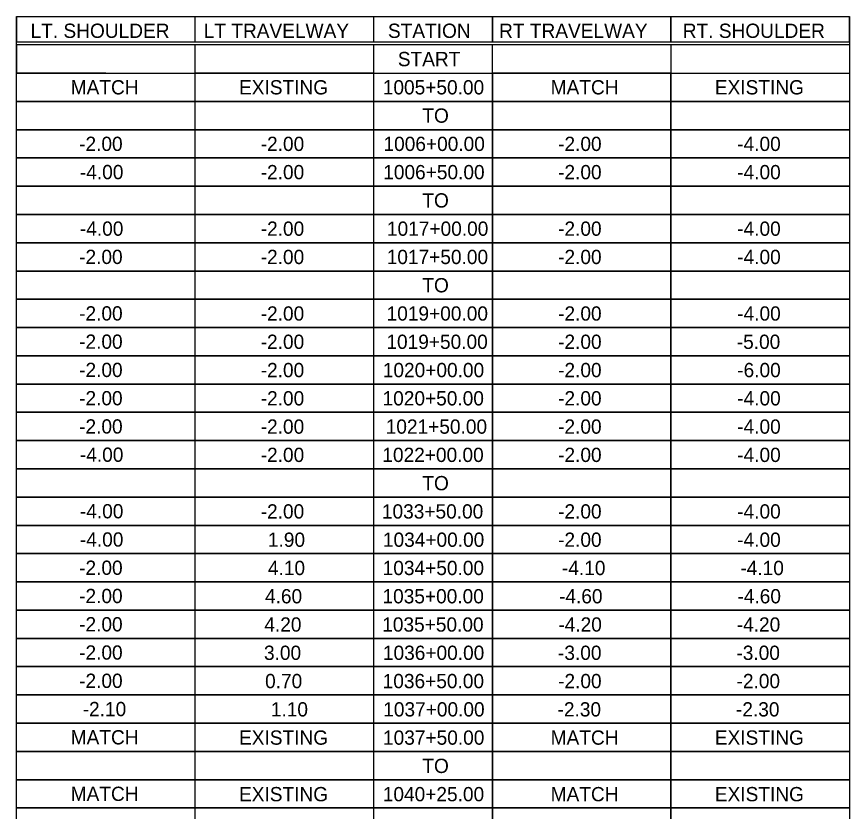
# Model space of a CAD drawing. Extents: x 1026502 to 1027102, y 781811 to 782040.
# Drawn here: x 1027034.42 to 1027062.42, y 781893.52 to 781920.24 of the extents above; entities that cross this region are included whole.
import ezdxf

# ---------------------------------------------------------------- set-up
doc = ezdxf.new("R2010")
doc.units = 0
for name, color, linetype in [('ANNOTATION', 7, 'Continuous'), ('BORDER', 7, 'Continuous'), ('DIMENSIONS', 7, 'Continuous')]:
    doc.layers.add(name, color=color, linetype=linetype)

msp = doc.modelspace()

# ---------------------------------------------------------------- linework, layer by layer
at = {"layer": 'ANNOTATION'}
msp.add_lwpolyline([(1027034.415, 781920.244), (1027062.415, 781920.244), (1027062.415, 781866.071), (1027034.415, 781866.071)], close=True, dxfattribs=at)
at = {"layer": 'BORDER'}
for p, q in [((1027034.415, 781920.244), (1027034.415, 781919.399)), ((1027037.415, 781919.293), (1027034.415, 781919.293)), ((1027034.415, 781919.293), (1027034.415, 781918.343)), ((1027062.415, 781919.293), (1027062.415, 781918.343)), ((1027037.415, 781918.343), (1027034.415, 781918.343)), ((1027037.415, 781918.343), (1027034.415, 781918.343)), ((1027037.415, 781917.393), (1027034.415, 781917.393)), ((1027037.415, 781917.393), (1027034.415, 781917.393)), ((1027037.415, 781917.393), (1027040.415, 781917.393)), ((1027037.415, 781916.442), (1027034.415, 781916.442)), ((1027037.415, 781916.442), (1027034.415, 781916.442)), ((1027037.415, 781916.442), (1027040.415, 781916.442)), ((1027037.415, 781915.492), (1027034.415, 781915.492)), ((1027037.415, 781915.492), (1027034.415, 781915.492)), ((1027037.415, 781915.492), (1027040.415, 781915.492)), ((1027037.415, 781914.541), (1027034.415, 781914.541)), ((1027037.415, 781914.541), (1027034.415, 781914.541)), ((1027037.415, 781914.541), (1027040.415, 781914.541)), ((1027037.415, 781913.591), (1027034.415, 781913.591)), ((1027037.415, 781913.591), (1027034.415, 781913.591)), ((1027037.415, 781913.591), (1027040.415, 781913.591)), ((1027037.415, 781912.641), (1027034.415, 781912.641)), ((1027037.415, 781912.641), (1027034.415, 781912.641)), ((1027037.415, 781912.641), (1027040.415, 781912.641)), ((1027037.415, 781911.69), (1027034.415, 781911.69)), ((1027037.415, 781911.69), (1027034.415, 781911.69)), ((1027037.415, 781911.69), (1027040.415, 781911.69)), ((1027037.415, 781910.74), (1027034.415, 781910.74)), ((1027037.415, 781910.74), (1027034.415, 781910.74)), ((1027037.415, 781910.74), (1027040.415, 781910.74)), ((1027037.415, 781909.789), (1027034.415, 781909.789)), ((1027037.415, 781909.789), (1027034.415, 781909.789)), ((1027037.415, 781909.789), (1027040.415, 781909.789)), ((1027037.415, 781908.839), (1027034.415, 781908.839)), ((1027037.415, 781908.839), (1027034.415, 781908.839)), ((1027037.415, 781908.839), (1027040.415, 781908.839)), ((1027037.415, 781907.889), (1027034.415, 781907.889)), ((1027037.415, 781907.889), (1027034.415, 781907.889)), ((1027037.415, 781907.889), (1027040.415, 781907.889)), ((1027037.415, 781906.938), (1027034.415, 781906.938)), ((1027037.415, 781906.938), (1027034.415, 781906.938)), ((1027037.415, 781906.938), (1027040.415, 781906.938)), ((1027037.415, 781905.988), (1027034.415, 781905.988)), ((1027037.415, 781905.988), (1027034.415, 781905.988)), ((1027037.415, 781905.988), (1027040.415, 781905.988)), ((1027037.415, 781905.037), (1027034.415, 781905.037)), ((1027037.415, 781905.037), (1027034.415, 781905.037)), ((1027037.415, 781905.037), (1027040.415, 781905.037)), ((1027037.415, 781904.087), (1027034.415, 781904.087)), ((1027037.415, 781904.087), (1027034.415, 781904.087)), ((1027037.415, 781904.087), (1027040.415, 781904.087)), ((1027037.415, 781903.137), (1027034.415, 781903.137)), ((1027037.415, 781903.137), (1027034.415, 781903.137)), ((1027037.415, 781903.137), (1027040.415, 781903.137)), ((1027037.415, 781902.186), (1027034.415, 781902.186)), ((1027037.415, 781902.186), (1027034.415, 781902.186)), ((1027037.415, 781902.186), (1027040.415, 781902.186)), ((1027037.415, 781901.236), (1027034.415, 781901.236)), ((1027037.415, 781901.236), (1027034.415, 781901.236)), ((1027037.415, 781901.236), (1027040.415, 781901.236)), ((1027037.415, 781900.285), (1027034.415, 781900.285)), ((1027037.415, 781900.285), (1027034.415, 781900.285)), ((1027037.415, 781900.285), (1027040.415, 781900.285)), ((1027037.415, 781899.335), (1027034.415, 781899.335)), ((1027037.415, 781899.335), (1027034.415, 781899.335)), ((1027037.415, 781899.335), (1027040.415, 781899.335)), ((1027037.415, 781898.385), (1027034.415, 781898.385)), ((1027037.415, 781898.385), (1027034.415, 781898.385)), ((1027037.415, 781898.385), (1027040.415, 781898.385)), ((1027037.415, 781897.434), (1027034.415, 781897.434)), ((1027037.415, 781897.434), (1027034.415, 781897.434)), ((1027037.415, 781897.434), (1027040.415, 781897.434)), ((1027037.415, 781896.484), (1027034.415, 781896.484)), ((1027037.415, 781896.484), (1027034.415, 781896.484)), ((1027037.415, 781896.484), (1027040.415, 781896.484)), ((1027037.415, 781895.533), (1027034.415, 781895.533)), ((1027037.415, 781895.533), (1027034.415, 781895.533)), ((1027037.415, 781895.533), (1027040.415, 781895.533)), ((1027037.415, 781894.583), (1027034.415, 781894.583)), ((1027037.415, 781894.583), (1027034.415, 781894.583)), ((1027037.415, 781894.583), (1027040.415, 781894.583)), ((1027037.415, 781893.633), (1027034.415, 781893.633)), ((1027037.415, 781893.633), (1027034.415, 781893.633)), ((1027037.415, 781893.633), (1027040.415, 781893.633))]:
    msp.add_line(p, q, dxfattribs=at)
for points in [[(1027034.415, 781920.244), (1027062.415, 781920.244), (1027062.415, 781919.293), (1027034.415, 781919.293)], [(1027034.415, 781918.343), (1027062.415, 781918.343), (1027062.415, 781917.393), (1027034.415, 781917.393)], [(1027034.415, 781917.393), (1027062.415, 781917.393), (1027062.415, 781916.442), (1027034.415, 781916.442)], [(1027034.415, 781916.442), (1027062.415, 781916.442), (1027062.415, 781915.492), (1027034.415, 781915.492)], [(1027034.415, 781915.492), (1027062.415, 781915.492), (1027062.415, 781914.541), (1027034.415, 781914.541)], [(1027034.415, 781914.541), (1027062.415, 781914.541), (1027062.415, 781913.591), (1027034.415, 781913.591)], [(1027034.415, 781913.591), (1027062.415, 781913.591), (1027062.415, 781912.641), (1027034.415, 781912.641)], [(1027034.415, 781912.641), (1027062.415, 781912.641), (1027062.415, 781911.69), (1027034.415, 781911.69)], [(1027034.415, 781911.69), (1027062.415, 781911.69), (1027062.415, 781910.74), (1027034.415, 781910.74)], [(1027034.415, 781910.74), (1027062.415, 781910.74), (1027062.415, 781909.789), (1027034.415, 781909.789)], [(1027034.415, 781909.789), (1027062.415, 781909.789), (1027062.415, 781908.839), (1027034.415, 781908.839)], [(1027034.415, 781908.839), (1027062.415, 781908.839), (1027062.415, 781907.889), (1027034.415, 781907.889)], [(1027034.415, 781907.889), (1027062.415, 781907.889), (1027062.415, 781906.938), (1027034.415, 781906.938)], [(1027034.415, 781906.938), (1027062.415, 781906.938), (1027062.415, 781905.988), (1027034.415, 781905.988)], [(1027034.415, 781905.988), (1027062.415, 781905.988), (1027062.415, 781905.037), (1027034.415, 781905.037)], [(1027034.415, 781905.037), (1027062.415, 781905.037), (1027062.415, 781904.087), (1027034.415, 781904.087)], [(1027034.415, 781904.087), (1027062.415, 781904.087), (1027062.415, 781903.137), (1027034.415, 781903.137)], [(1027034.415, 781903.137), (1027062.415, 781903.137), (1027062.415, 781902.186), (1027034.415, 781902.186)], [(1027034.415, 781902.186), (1027062.415, 781902.186), (1027062.415, 781901.236), (1027034.415, 781901.236)], [(1027034.415, 781901.236), (1027062.415, 781901.236), (1027062.415, 781900.285), (1027034.415, 781900.285)], [(1027034.415, 781900.285), (1027062.415, 781900.285), (1027062.415, 781899.335), (1027034.415, 781899.335)], [(1027034.415, 781899.335), (1027062.415, 781899.335), (1027062.415, 781898.385), (1027034.415, 781898.385)], [(1027034.415, 781898.385), (1027062.415, 781898.385), (1027062.415, 781897.434), (1027034.415, 781897.434)], [(1027034.415, 781897.434), (1027062.415, 781897.434), (1027062.415, 781896.484), (1027034.415, 781896.484)], [(1027034.415, 781896.484), (1027062.415, 781896.484), (1027062.415, 781895.533), (1027034.415, 781895.533)], [(1027034.415, 781895.533), (1027062.415, 781895.533), (1027062.415, 781894.583), (1027034.415, 781894.583)], [(1027034.415, 781894.583), (1027062.415, 781894.583), (1027062.415, 781893.633), (1027034.415, 781893.633)], [(1027034.415, 781893.633), (1027062.415, 781893.633), (1027062.415, 781892.682), (1027034.415, 781892.682)]]:
    msp.add_lwpolyline(points, close=True, dxfattribs=at)
for points in [[(1027034.415, 781919.399), (1027062.415, 781919.399), (1027062.415, 781920.244)], [(1027040.415, 781919.399), (1027040.415, 781920.244)], [(1027046.415, 781920.244), (1027046.415, 781919.399)], [(1027050.415, 781920.244), (1027050.415, 781919.399)], [(1027050.415, 781919.399), (1027050.415, 781920.244)], [(1027056.415, 781920.244), (1027056.415, 781919.399)], [(1027056.415, 781919.399), (1027056.415, 781920.244)], [(1027062.415, 781920.244), (1027062.415, 781919.399)], [(1027046.415, 781919.293), (1027046.415, 781918.343), (1027040.415, 781918.343), (1027040.415, 781919.293)], [(1027056.415, 781919.293), (1027056.415, 781918.343), (1027050.415, 781918.343), (1027050.415, 781919.293)], [(1027046.415, 781918.343), (1027046.415, 781917.393), (1027040.415, 781917.393), (1027040.415, 781918.343)], [(1027050.415, 781918.343), (1027050.415, 781917.393), (1027046.415, 781917.393)], [(1027056.415, 781918.343), (1027056.415, 781917.393), (1027050.415, 781917.393), (1027050.415, 781918.343)], [(1027062.415, 781918.343), (1027062.415, 781917.393), (1027056.415, 781917.393), (1027056.415, 781918.343)], [(1027046.415, 781917.393), (1027046.415, 781916.442), (1027040.415, 781916.442), (1027040.415, 781917.393)], [(1027050.415, 781917.393), (1027050.415, 781916.442), (1027046.415, 781916.442)], [(1027056.415, 781917.393), (1027056.415, 781916.442), (1027050.415, 781916.442), (1027050.415, 781917.393)], [(1027062.415, 781917.393), (1027062.415, 781916.442), (1027056.415, 781916.442), (1027056.415, 781917.393)], [(1027046.415, 781916.442), (1027046.415, 781915.492), (1027040.415, 781915.492), (1027040.415, 781916.442)], [(1027050.415, 781916.442), (1027050.415, 781915.492), (1027046.415, 781915.492)], [(1027056.415, 781916.442), (1027056.415, 781915.492), (1027050.415, 781915.492), (1027050.415, 781916.442)], [(1027062.415, 781916.442), (1027062.415, 781915.492), (1027056.415, 781915.492), (1027056.415, 781916.442)], [(1027046.415, 781915.492), (1027046.415, 781914.541), (1027040.415, 781914.541), (1027040.415, 781915.492)], [(1027050.415, 781915.492), (1027050.415, 781914.541), (1027046.415, 781914.541)], [(1027056.415, 781915.492), (1027056.415, 781914.541), (1027050.415, 781914.541), (1027050.415, 781915.492)], [(1027062.415, 781915.492), (1027062.415, 781914.541), (1027056.415, 781914.541), (1027056.415, 781915.492)], [(1027046.415, 781914.541), (1027046.415, 781913.591), (1027040.415, 781913.591), (1027040.415, 781914.541)], [(1027050.415, 781914.541), (1027050.415, 781913.591), (1027046.415, 781913.591)], [(1027056.415, 781914.541), (1027056.415, 781913.591), (1027050.415, 781913.591), (1027050.415, 781914.541)], [(1027062.415, 781914.541), (1027062.415, 781913.591), (1027056.415, 781913.591), (1027056.415, 781914.541)], [(1027046.415, 781913.591), (1027046.415, 781912.641), (1027040.415, 781912.641), (1027040.415, 781913.591)], [(1027050.415, 781913.591), (1027050.415, 781912.641), (1027046.415, 781912.641)], [(1027056.415, 781913.591), (1027056.415, 781912.641), (1027050.415, 781912.641), (1027050.415, 781913.591)], [(1027062.415, 781913.591), (1027062.415, 781912.641), (1027056.415, 781912.641), (1027056.415, 781913.591)], [(1027046.415, 781912.641), (1027046.415, 781911.69), (1027040.415, 781911.69), (1027040.415, 781912.641)], [(1027050.415, 781912.641), (1027050.415, 781911.69), (1027046.415, 781911.69)], [(1027056.415, 781912.641), (1027056.415, 781911.69), (1027050.415, 781911.69), (1027050.415, 781912.641)], [(1027062.415, 781912.641), (1027062.415, 781911.69), (1027056.415, 781911.69), (1027056.415, 781912.641)], [(1027046.415, 781911.69), (1027046.415, 781910.74), (1027040.415, 781910.74), (1027040.415, 781911.69)], [(1027050.415, 781911.69), (1027050.415, 781910.74), (1027046.415, 781910.74)], [(1027056.415, 781911.69), (1027056.415, 781910.74), (1027050.415, 781910.74), (1027050.415, 781911.69)], [(1027062.415, 781911.69), (1027062.415, 781910.74), (1027056.415, 781910.74), (1027056.415, 781911.69)], [(1027046.415, 781910.74), (1027046.415, 781909.789), (1027040.415, 781909.789), (1027040.415, 781910.74)], [(1027050.415, 781910.74), (1027050.415, 781909.789), (1027046.415, 781909.789)], [(1027056.415, 781910.74), (1027056.415, 781909.789), (1027050.415, 781909.789), (1027050.415, 781910.74)], [(1027062.415, 781910.74), (1027062.415, 781909.789), (1027056.415, 781909.789), (1027056.415, 781910.74)], [(1027046.415, 781909.789), (1027046.415, 781908.839), (1027040.415, 781908.839), (1027040.415, 781909.789)], [(1027050.415, 781909.789), (1027050.415, 781908.839), (1027046.415, 781908.839)], [(1027056.415, 781909.789), (1027056.415, 781908.839), (1027050.415, 781908.839), (1027050.415, 781909.789)], [(1027062.415, 781909.789), (1027062.415, 781908.839), (1027056.415, 781908.839), (1027056.415, 781909.789)], [(1027046.415, 781908.839), (1027046.415, 781907.889), (1027040.415, 781907.889), (1027040.415, 781908.839)], [(1027050.415, 781908.839), (1027050.415, 781907.889), (1027046.415, 781907.889)], [(1027056.415, 781908.839), (1027056.415, 781907.889), (1027050.415, 781907.889), (1027050.415, 781908.839)], [(1027062.415, 781908.839), (1027062.415, 781907.889), (1027056.415, 781907.889), (1027056.415, 781908.839)], [(1027046.415, 781907.889), (1027046.415, 781906.938), (1027040.415, 781906.938), (1027040.415, 781907.889)], [(1027050.415, 781907.889), (1027050.415, 781906.938), (1027046.415, 781906.938)], [(1027056.415, 781907.889), (1027056.415, 781906.938), (1027050.415, 781906.938), (1027050.415, 781907.889)], [(1027062.415, 781907.889), (1027062.415, 781906.938), (1027056.415, 781906.938), (1027056.415, 781907.889)], [(1027046.415, 781906.938), (1027046.415, 781905.988), (1027040.415, 781905.988), (1027040.415, 781906.938)], [(1027050.415, 781906.938), (1027050.415, 781905.988), (1027046.415, 781905.988)], [(1027056.415, 781906.938), (1027056.415, 781905.988), (1027050.415, 781905.988), (1027050.415, 781906.938)], [(1027062.415, 781906.938), (1027062.415, 781905.988), (1027056.415, 781905.988), (1027056.415, 781906.938)], [(1027046.415, 781905.988), (1027046.415, 781905.037), (1027040.415, 781905.037), (1027040.415, 781905.988)], [(1027050.415, 781905.988), (1027050.415, 781905.037), (1027046.415, 781905.037)], [(1027056.415, 781905.988), (1027056.415, 781905.037), (1027050.415, 781905.037), (1027050.415, 781905.988)], [(1027062.415, 781905.988), (1027062.415, 781905.037), (1027056.415, 781905.037), (1027056.415, 781905.988)], [(1027046.415, 781905.037), (1027046.415, 781904.087), (1027040.415, 781904.087), (1027040.415, 781905.037)], [(1027050.415, 781905.037), (1027050.415, 781904.087), (1027046.415, 781904.087)], [(1027056.415, 781905.037), (1027056.415, 781904.087), (1027050.415, 781904.087), (1027050.415, 781905.037)], [(1027062.415, 781905.037), (1027062.415, 781904.087), (1027056.415, 781904.087), (1027056.415, 781905.037)], [(1027046.415, 781904.087), (1027046.415, 781903.137), (1027040.415, 781903.137), (1027040.415, 781904.087)], [(1027050.415, 781904.087), (1027050.415, 781903.137), (1027046.415, 781903.137)], [(1027056.415, 781904.087), (1027056.415, 781903.137), (1027050.415, 781903.137), (1027050.415, 781904.087)], [(1027062.415, 781904.087), (1027062.415, 781903.137), (1027056.415, 781903.137), (1027056.415, 781904.087)], [(1027046.415, 781903.137), (1027046.415, 781902.186), (1027040.415, 781902.186), (1027040.415, 781903.137)], [(1027050.415, 781903.137), (1027050.415, 781902.186), (1027046.415, 781902.186)], [(1027056.415, 781903.137), (1027056.415, 781902.186), (1027050.415, 781902.186), (1027050.415, 781903.137)], [(1027062.415, 781903.137), (1027062.415, 781902.186), (1027056.415, 781902.186), (1027056.415, 781903.137)], [(1027046.415, 781902.186), (1027046.415, 781901.236), (1027040.415, 781901.236), (1027040.415, 781902.186)], [(1027050.415, 781902.186), (1027050.415, 781901.236), (1027046.415, 781901.236)], [(1027056.415, 781902.186), (1027056.415, 781901.236), (1027050.415, 781901.236), (1027050.415, 781902.186)], [(1027062.415, 781902.186), (1027062.415, 781901.236), (1027056.415, 781901.236), (1027056.415, 781902.186)], [(1027046.415, 781901.236), (1027046.415, 781900.285), (1027040.415, 781900.285), (1027040.415, 781901.236)], [(1027050.415, 781901.236), (1027050.415, 781900.285), (1027046.415, 781900.285)], [(1027056.415, 781901.236), (1027056.415, 781900.285), (1027050.415, 781900.285), (1027050.415, 781901.236)], [(1027062.415, 781901.236), (1027062.415, 781900.285), (1027056.415, 781900.285), (1027056.415, 781901.236)], [(1027046.415, 781900.285), (1027046.415, 781899.335), (1027040.415, 781899.335), (1027040.415, 781900.285)], [(1027050.415, 781900.285), (1027050.415, 781899.335), (1027046.415, 781899.335)], [(1027056.415, 781900.285), (1027056.415, 781899.335), (1027050.415, 781899.335), (1027050.415, 781900.285)], [(1027062.415, 781900.285), (1027062.415, 781899.335), (1027056.415, 781899.335), (1027056.415, 781900.285)], [(1027046.415, 781899.335), (1027046.415, 781898.385), (1027040.415, 781898.385), (1027040.415, 781899.335)], [(1027050.415, 781899.335), (1027050.415, 781898.385), (1027046.415, 781898.385)], [(1027056.415, 781899.335), (1027056.415, 781898.385), (1027050.415, 781898.385), (1027050.415, 781899.335)], [(1027062.415, 781899.335), (1027062.415, 781898.385), (1027056.415, 781898.385), (1027056.415, 781899.335)], [(1027046.415, 781898.385), (1027046.415, 781897.434), (1027040.415, 781897.434), (1027040.415, 781898.385)], [(1027050.415, 781898.385), (1027050.415, 781897.434), (1027046.415, 781897.434)], [(1027056.415, 781898.385), (1027056.415, 781897.434), (1027050.415, 781897.434), (1027050.415, 781898.385)], [(1027062.415, 781898.385), (1027062.415, 781897.434), (1027056.415, 781897.434), (1027056.415, 781898.385)], [(1027046.415, 781897.434), (1027046.415, 781896.484), (1027040.415, 781896.484), (1027040.415, 781897.434)], [(1027050.415, 781897.434), (1027050.415, 781896.484), (1027046.415, 781896.484)], [(1027056.415, 781897.434), (1027056.415, 781896.484), (1027050.415, 781896.484), (1027050.415, 781897.434)], [(1027062.415, 781897.434), (1027062.415, 781896.484), (1027056.415, 781896.484), (1027056.415, 781897.434)], [(1027046.415, 781896.484), (1027046.415, 781895.533), (1027040.415, 781895.533), (1027040.415, 781896.484)], [(1027050.415, 781896.484), (1027050.415, 781895.533), (1027046.415, 781895.533)], [(1027056.415, 781896.484), (1027056.415, 781895.533), (1027050.415, 781895.533), (1027050.415, 781896.484)], [(1027062.415, 781896.484), (1027062.415, 781895.533), (1027056.415, 781895.533), (1027056.415, 781896.484)], [(1027046.415, 781895.533), (1027046.415, 781894.583), (1027040.415, 781894.583), (1027040.415, 781895.533)], [(1027050.415, 781895.533), (1027050.415, 781894.583), (1027046.415, 781894.583)], [(1027056.415, 781895.533), (1027056.415, 781894.583), (1027050.415, 781894.583), (1027050.415, 781895.533)], [(1027062.415, 781895.533), (1027062.415, 781894.583), (1027056.415, 781894.583), (1027056.415, 781895.533)], [(1027046.415, 781894.583), (1027046.415, 781893.633), (1027040.415, 781893.633), (1027040.415, 781894.583)], [(1027050.415, 781894.583), (1027050.415, 781893.633), (1027046.415, 781893.633)], [(1027056.415, 781894.583), (1027056.415, 781893.633), (1027050.415, 781893.633), (1027050.415, 781894.583)], [(1027062.415, 781894.583), (1027062.415, 781893.633), (1027056.415, 781893.633), (1027056.415, 781894.583)], [(1027046.415, 781893.633), (1027046.415, 781892.682), (1027040.415, 781892.682), (1027040.415, 781893.633)], [(1027050.415, 781893.633), (1027050.415, 781892.682), (1027046.415, 781892.682)], [(1027056.415, 781893.633), (1027056.415, 781892.682), (1027050.415, 781892.682), (1027050.415, 781893.633)], [(1027062.415, 781893.633), (1027062.415, 781892.682), (1027056.415, 781892.682), (1027056.415, 781893.633)]]:
    msp.add_lwpolyline(points, dxfattribs=at)

# ---------------------------------------------------------------- texts
at = {"layer": 'DIMENSIONS'}
for s, p in [('LT. SHOULDER', (1027034.883, 781919.529)), ('LT TRAVELWAY', (1027040.706, 781919.529)), ('STATION', (1027046.9, 781919.529)), ('RT TRAVELWAY', (1027050.638, 781919.529)), ('RT. SHOULDER', (1027056.814, 781919.529)), ('START', (1027047.232, 781918.578)), ('MATCH', (1027036.233, 781917.628)), ('EXISTING', (1027041.892, 781917.628)), ('1005+50.00', (1027046.727, 781917.628)), ('MATCH', (1027052.372, 781917.628)), ('EXISTING', (1027057.892, 781917.628)), ('TO', (1027048.057, 781916.677)), ('-2.00', (1027036.516, 781915.727)), ('-2.00', (1027042.622, 781915.726)), ('1006+00.00', (1027046.75, 781915.726)), ('-2.00', (1027052.622, 781915.726)), ('-4.00', (1027058.645, 781915.726)), ('-4.00', (1027036.542, 781914.777)), ('-2.00', (1027042.622, 781914.775)), ('1006+50.00', (1027046.742, 781914.775)), ('-2.00', (1027052.622, 781914.775)), ('-4.00', (1027058.645, 781914.775)), ('TO', (1027048.057, 781913.824)), ('-4.00', (1027036.542, 781912.876)), ('-2.00', (1027042.622, 781912.874)), ('1017+00.00', (1027046.867, 781912.874)), ('-2.00', (1027052.622, 781912.874)), ('-4.00', (1027058.645, 781912.874)), ('-2.00', (1027036.516, 781911.925)), ('-2.00', (1027042.622, 781911.923)), ('1017+50.00', (1027046.859, 781911.923)), ('-2.00', (1027052.622, 781911.923)), ('-4.00', (1027058.645, 781911.923)), ('TO', (1027048.057, 781910.972)), ('-2.00', (1027036.516, 781910.025)), ('-2.00', (1027042.622, 781910.021)), ('1019+00.00', (1027046.855, 781910.021)), ('-2.00', (1027052.622, 781910.021)), ('-4.00', (1027058.645, 781910.021)), ('-2.00', (1027036.516, 781909.074)), ('-2.00', (1027042.622, 781909.07)), ('1019+50.00', (1027046.848, 781909.07)), ('-2.00', (1027052.622, 781909.07)), ('-5.00', (1027058.63, 781909.07)), ('-2.00', (1027036.516, 781908.124)), ('-2.00', (1027042.622, 781908.119)), ('1020+00.00', (1027046.727, 781908.119)), ('-2.00', (1027052.622, 781908.119)), ('-6.00', (1027058.645, 781908.119)), ('-2.00', (1027036.516, 781907.173)), ('-2.00', (1027042.622, 781907.169)), ('1020+50.00', (1027046.719, 781907.169)), ('-2.00', (1027052.622, 781907.169)), ('-4.00', (1027058.645, 781907.169)), ('-2.00', (1027036.516, 781906.223)), ('-2.00', (1027042.622, 781906.218)), ('1021+50.00', (1027046.825, 781906.218)), ('-2.00', (1027052.622, 781906.218)), ('-4.00', (1027058.645, 781906.218)), ('-4.00', (1027036.542, 781905.273)), ('-2.00', (1027042.622, 781905.267)), ('1022+00.00', (1027046.712, 781905.267)), ('-2.00', (1027052.622, 781905.267)), ('-4.00', (1027058.645, 781905.267)), ('TO', (1027048.057, 781904.316)), ('-4.00', (1027036.542, 781903.372)), ('-2.00', (1027042.622, 781903.365)), ('1033+50.00', (1027046.697, 781903.365)), ('-2.00', (1027052.622, 781903.365)), ('-4.00', (1027058.645, 781903.365)), ('-4.00', (1027036.542, 781902.421)), ('1.90', (1027042.864, 781902.414)), ('1034+00.00', (1027046.731, 781902.414)), ('-2.00', (1027052.622, 781902.414)), ('-4.00', (1027058.645, 781902.414)), ('-2.00', (1027036.516, 781901.471)), ('4.10', (1027042.864, 781901.464)), ('1034+50.00', (1027046.723, 781901.464)), ('-4.10', (1027052.751, 781901.464)), ('-4.10', (1027058.751, 781901.464)), ('-2.00', (1027036.516, 781900.521)), ('4.60', (1027042.766, 781900.513)), ('1035+00.00', (1027046.716, 781900.513)), ('-4.60', (1027052.653, 781900.513)), ('-4.60', (1027058.653, 781900.513)), ('-2.00', (1027036.516, 781899.57)), ('4.20', (1027042.743, 781899.562)), ('1035+50.00', (1027046.708, 781899.562)), ('-4.20', (1027052.63, 781899.562)), ('-4.20', (1027058.63, 781899.562)), ('-2.00', (1027036.516, 781898.62)), ('3.00', (1027042.732, 781898.611)), ('1036+00.00', (1027046.731, 781898.611)), ('-3.00', (1027052.618, 781898.611)), ('-3.00', (1027058.618, 781898.611)), ('-2.00', (1027036.516, 781897.669)), ('0.70', (1027042.769, 781897.66)), ('1036+50.00', (1027046.723, 781897.66)), ('-2.00', (1027052.622, 781897.66)), ('-2.00', (1027058.622, 781897.66)), ('-2.10', (1027036.636, 781896.719)), ('1.10', (1027042.962, 781896.709)), ('1037+00.00', (1027046.742, 781896.709)), ('-2.30', (1027052.603, 781896.709)), ('-2.30', (1027058.603, 781896.709)), ('MATCH', (1027036.233, 781895.769)), ('EXISTING', (1027041.892, 781895.759)), ('1037+50.00', (1027046.734, 781895.759)), ('MATCH', (1027052.372, 781895.759)), ('EXISTING', (1027057.892, 781895.759)), ('TO', (1027048.057, 781894.808)), ('MATCH', (1027036.233, 781893.868)), ('EXISTING', (1027041.892, 781893.857)), ('1040+25.00', (1027046.727, 781893.857)), ('MATCH', (1027052.372, 781893.857)), ('EXISTING', (1027057.892, 781893.857))]:
    msp.add_text(s, height=0.48, dxfattribs=at).set_placement(p)

doc.saveas('drawing.dxf')
